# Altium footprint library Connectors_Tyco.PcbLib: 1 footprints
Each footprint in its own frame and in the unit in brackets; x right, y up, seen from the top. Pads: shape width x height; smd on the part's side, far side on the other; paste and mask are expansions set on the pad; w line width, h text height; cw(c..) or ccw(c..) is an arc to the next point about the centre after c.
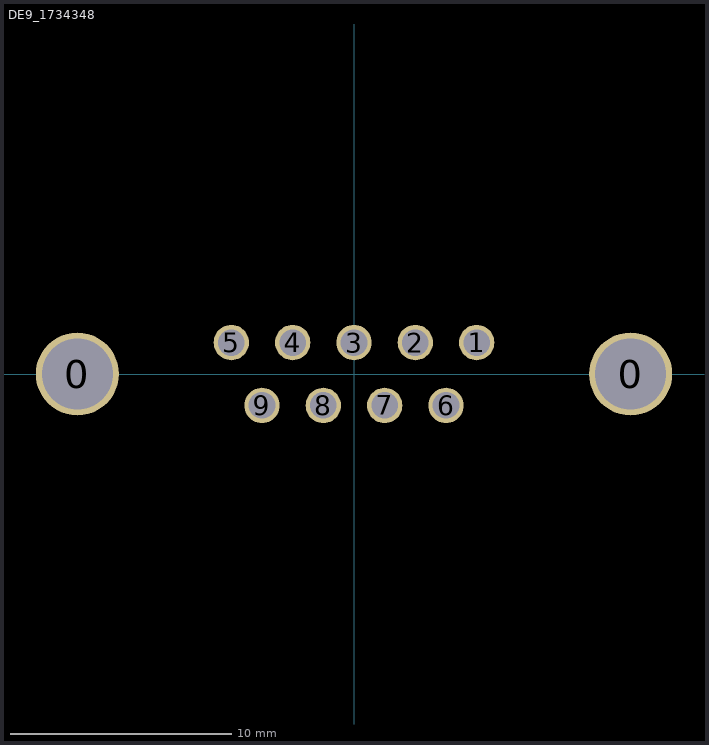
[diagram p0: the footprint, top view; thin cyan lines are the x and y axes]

## DE9_1734348 [mm]
height 12.5
pads (11):
  round 3.75 hole 3.2: 0(-12.495,0) 0(12.495,0)
  round 1.6 hole 1.2: 1(5.54,1.42) 2(2.77,1.42) 3(0,1.42) 4(-2.77,1.42) 5(-5.54,1.42) 6(4.155,-1.42) 7(1.385,-1.42) 8(-1.385,-1.42) 9(-4.155,-1.42)
3D body: height 12.5, standoff 0, extent -15,-9.5 15,3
